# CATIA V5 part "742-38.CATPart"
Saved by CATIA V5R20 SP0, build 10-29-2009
Part number: 742-38
Bounding box of the stored display mesh (mm): x -33 to 33.5, y -32.999 to 32.999, z -37 to 71
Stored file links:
  C:\Users\Utente\Desktop\IO LAVORO\3D X SITO CF\X SITO\742\742-38.CATPart
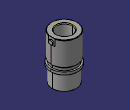
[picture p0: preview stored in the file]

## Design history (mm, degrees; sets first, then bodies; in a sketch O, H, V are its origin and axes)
Set1
  DatumSurface1 to DatumSurface38 "742-38"
Body1 (main body)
